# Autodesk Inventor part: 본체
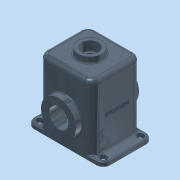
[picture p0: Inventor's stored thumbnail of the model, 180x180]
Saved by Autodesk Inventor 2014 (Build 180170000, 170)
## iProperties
Company: 한국ATC센터
Created: 2014-10
Part Number: 본체
Document SubType Name: Modeling
Designer: 한국ATC센터
Density: 2.71 g/cm^3
Material: 알루미늄 6061
Mass: 3285.47 g
Surface Area: 2358.49 cm^2
Volume: 1212.35 cm^3
Appearance: 청회색(진함/광택)
Author: KYOUNG IL JANG
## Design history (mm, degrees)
sketch "스케치1"
  geometry: L1 (-70, 65)-(70, 65); L2 (70, 65)-(70, -65); L3 (70, -65)-(-70, -65); L4 (-70, -65)-(-70, 65); 3 further points
  constraints: 8 end point, 2 midpoint, 2 parallel, 1 horizontal, 1 horizontal alignment, 1 perpendicular, 1 vertical alignment
  dimensions: "d0" = 140 distance of L2.end L3.end; "d68" = 130 distance of L3.end L1.start
extrude "돌출1" new body sketch "스케치1" distance "d1" = 180; taper "d2" = 0 deg
fillet "모깎기1" dims "d3" = 20
feature "쉘1" dims "d4" = 10
sketch "스케치2"
  geometry: L1 (-70, 45)-(-70, -45) reference; L2 (-50, -65)-(-82, -65); L3 (-82, 65)-(-50, 65); L4 (-85, 57)-(-82, 57); L5 (-82, 41)-(-85, 41); L6 (-100, 47)-(-100, -47); A1 r 20 centre (-50, 45) between (-50, 65) and (-70, 45) reference; A2 r 20 centre (-50, -45) between (-70, -45) and (-50, -65) reference; A3 r 8 centre (-82, 49) between (-82, 41) and (-82, 57); A4 r 8 centre (-85, 49) between (-85, 57) and (-85, 41); A5 r 18 centre (-82, 47) between (-82, 65) and (-100, 47); A6 r 18 centre (-82, -47) between (-100, -47) and (-82, -65); 1 further point
  constraints: 10 end point, 9 tangent, 8 point on circle, 4 centre point, 2 parallel, 2 perpendicular, 1 equal radius
  dimensions: "d6" = 49 vertical distance of point (0, 0) A3.centre; "d8" = 16 distance between parallel lines of L4 L5; "d64" = 18 radius of A5; "d65" = 12 distance from line of A3.centre L1; "d66" = 30 distance between parallel lines of L6 L1; "d67" = 3 distance of A4.centre A3.centre
extrude "돌출2" join sketch "스케치2" distance "d9" = 10; taper "d10" = 0 deg
extrude "돌출3" cut sketch "스케치2" stored distance "d11" = 10; taper "d12" = 0 deg
sketch "스케치3"
  geometry: L1 (-65, 0)-(-65, 180) reference; L2 (-55, 0)-(-55, 170) reference; L3 (-83, 75)-(-51, 75); L4 (45, 0)-(-45, 0) reference; L5 (-83, 75)-(-83, 120.5); L6 (-83, 120.5)-(-55, 120.5); L7 (-55, 120.5)-(-51, 116.5); L8 (-51, 116.5)-(-51, 75); 2 further points
  constraints: 10 end point, 4 perpendicular, 1 point on line
  dimensions: "d13" = 75 distance between parallel lines of L3 L4; "d14" = 18 distance from line of L1 L3.start; "d15" = 4 distance from line of L3.end L2; "d16" = 91 diameter of L6 L3; "d17" = 135 deg angle of L7 L2
revolve "회전1" sketch "스케치3" stored, may be unused: angle "d18" = 90 deg
sketch "스케치4"
  geometry: C1 r 45.5 at (0, 0) reference; 2 further points
  constraints: 1 vertical alignment
  dimensions: "d19" = 35 distance of C1.centre point (0, 35)
hole "구멍1" sketch "스케치4" at (0, 35) diameter "d20" = 3.459; stored, may be unused: countersink angle "d24" = 90 deg, drill point angle "d26" = 118 deg; dims "d21" = 13, "d22" = 4, "d23" = 2, "d25" = 16
fillet "모깎기2" dims "d30" = 3
hole "구멍2" diameter "d33" = 52; stored, may be unused: countersink angle "d37" = 90 deg, drill point angle "d39" = 118 deg; dims "d31" = 10, "d32" = 10, "d34" = 13, "d35" = 4, "d36" = 2, "d38" = 16
sketch "스케치5"
  geometry: C1 r 31 at (0, 0); 1 further point
  constraints: 1 centre point, 1 coincident
  dimensions: "d40" = 62 diameter of C1
extrude "돌출4" join sketch "스케치5" distance "d41" = 15; taper "d42" = 0 deg
hole "구멍3" diameter "d45" = 43; stored, may be unused: countersink angle "d49" = 90 deg, drill point angle "d51" = 118 deg; dims "d43" = 10, "d44" = 10, "d46" = 13, "d47" = 4, "d48" = 2, "d50" = 16
fillet "모깎기3" dims "d52" = 3
fillet "모깎기4" dims "d53" = 3
chamfer "모따기1" distance "d55" = 1; stored, may be unused: second distance "d56" = 2, angle "d57" = 45 deg
sketch "스케치6"
  geometry: 2 further points
  constraints: 1 vertical alignment, 1 other
  dimensions: "d71" = 90 distance of point (0, 0) point (0, 90)
feature "엠보싱2" sketch "스케치6" dims "d0" = 140, "d68" = 130, "d72" = 1, "d73" = 0
fillet "모깎기6" dims "d74" = 10
sketch "스케치7"
  geometry: C1 r 15 at (0, 0); C2 r 21.5 at (0, 0) reference; C3 r 25 at (0, 0); 1 further point
  constraints: 2 centre point, 2 coincident
  dimensions: "d61" = 30 diameter of C1; "d75" = 50 diameter of C3
extrude "돌출5" join sketch "스케치7" distance "d62" = 10; taper "d63" = 0 deg
feature "면 이동1" dims "d76" = 1
fillet "모깎기7" dims "d77" = 3
node "솔리드1"
mirror "대칭1"
mirror "대칭2"
pattern_circular "원형 패턴1" dims angle "d28" = 360 deg
mirror "대칭3"
